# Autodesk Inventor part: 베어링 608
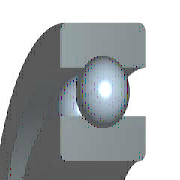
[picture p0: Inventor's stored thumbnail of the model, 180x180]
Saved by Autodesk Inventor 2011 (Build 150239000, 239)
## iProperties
IsCustomPart: 1
Company: 한국ATC센터
Created: 2014-07
Part Number: 베어링 608
Material: 강, 연강
Description: 깊은 그루브 볼 베어링
Document SubType Name: Modeling
Standard: KS B 2023
Designer: KYOUNG IL JANG
Standards Organization: KS
Language: ko-KR
Size Designation: 608 - 8 x 22 x 7
Categories: <MemberInstance><Categories><Category DisplayName="샤프트 부품" InternalName="7f7aeb1f-a693-4053-b835-cee3144e0d98" Mnemonic="SHFT"><Category DisplayName="베어링" Inter
Density: 1 g/cm^3
Author: KYOUNG IL JANG
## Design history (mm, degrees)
revolve "본체" stored, may be unused: angle "d6" = 90 deg
revolve "볼" stored, may be unused: angle "d7" = 90 deg
pattern_circular "IDS_ARRAYBALL[SIMPL:T]" dims angle "d3" = 360 deg
body "Solid1"
sketch "스케치" dims "d0" = 3.64 (= -0.26 x WD + 0.26 x BD)
  geometry: L1 (1.68, 7.5)-(5.32, 7.5); L2 (3.5, 7.5)-(3.5, 5.68); L3 (3.5, 7.5)-(3.5, 9.32); L4 (2.148, 6.282)-(0, 6.282); L5 (0, 4)-(7, 4); L6 (2.148, 8.718)-(0, 8.718); L7 (0, 11)-(7, 11); L8 (7, 4)-(7, 6.282); L9 (4.852, 6.282)-(7, 6.282); L10 (4.852, 8.718)-(7, 8.718); L11 (7, 11)-(7, 8.718); L12 (-1.4, 0)-(8.4, 0) reference; L13 (0, -0.3)-(0, 5.3) reference
  constraints: 22 end point, 4 point on line, 2 collinear, 2 perpendicular, 2 symmetric about line, 1 midpoint, 1 parallel, 14 other
  dimensions: "d9" = 8 diameter of L5 L12 (= WD); "d11" = 22 diameter of L7 L12 (= BD); "d12" = 7 distance between parallel lines of L8 L13 (= KB); "d13" = 12.564 diameter of L9 L12 (= 0.326 x BD + 0.674 x WD)
fillet "모깎기1" dims "d1" = 0.3 (= KRS)
other parameters: "WD" = 8 [user parameter; used in 5 equation terms], "BD" = 22 [user parameter; used in 5 equation terms], "KB" = 7 [user parameter; used in 1 equation term], "KRS" = 0.3 [user parameter; used in 1 equation term], "d4" = 0, "d5" = 0, "d8" = 0, "d14" = 0, "d15" = 0, "BBA" = 0 [user parameter], "BC0" = 1370000 [user parameter], "BC" = 3250000 [user parameter], "BR" = 11 (= 0.5 x BD) [user parameter], "WR" = 4 (= 0.5 x WD) [user parameter]
